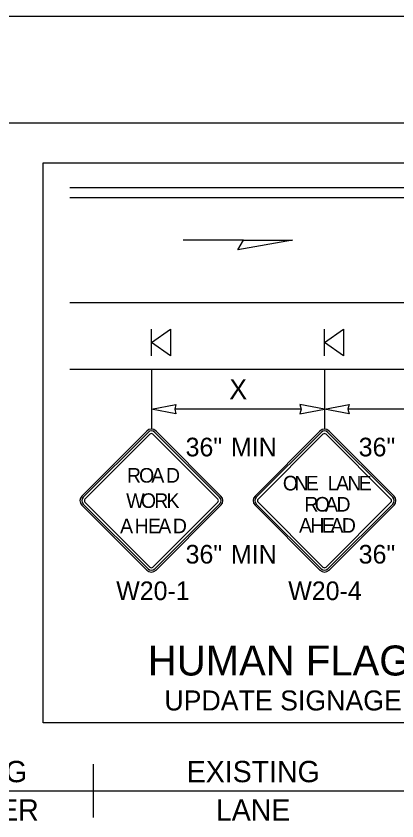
# Model space of a CAD drawing. Extents: x 99999.1 to 100095.7, y 99995 to 100010.7.
# Drawn here: x 100005 to 100006.43, y 100003.112 to 100006.132 of the extents above; entities that cross this region are included whole.
import ezdxf

# ---------------------------------------------------------------- set-up
doc = ezdxf.new("R2010")
doc.units = 0
for name, color, linetype in [('RD_ED_ShoulderPavedEdge', 7, 'Continuous'), ('RD_MK_LineDblYellowCenter', 7, 'Continuous'), ('RD_MK_LineEdgeWhite', 7, 'Continuous'), ('SH_DE_DetailHeading2Text', 7, 'Continuous'), ('TR_SN_ConstructionSigns', 7, 'Continuous'), ('TR_WZ_PortableSignMountBlk-Org', 7, 'Continuous'), ('TR_WZ_WorkZoneDetails', 7, 'Continuous'), ('TR_WZ_WorkZoneTextCurrent', 7, 'Continuous')]:
    doc.layers.add(name, color=color, linetype=linetype)

msp = doc.modelspace()

# ---------------------------------------------------------------- linework, layer by layer
at = {"layer": 'RD_ED_ShoulderPavedEdge'}
for p, q in [((100000.1076, 100005.7323), (100015.6424, 100005.7323)), ((100005.2015, 100004.8073), (100008.9925, 100004.8073))]:
    msp.add_line(p, q, dxfattribs=at)
at = {"layer": 'RD_MK_LineDblYellowCenter'}
for p, q in [((100005.2015, 100005.4886), (100008.0081, 100005.4886)), ((100005.2015, 100005.4511), (100008.0081, 100005.4511))]:
    msp.add_line(p, q, dxfattribs=at)
at = {"layer": 'RD_MK_LineEdgeWhite'}
for p, q in [((100000.1076, 100006.1323), (100015.6424, 100006.1323)), ((100005.2015, 100005.0573), (100008.9925, 100005.0573))]:
    msp.add_line(p, q, dxfattribs=at)
at = {"layer": 'TR_SN_ConstructionSigns'}
for p, q in [((100005.4907, 100004.5751), (100005.2471, 100004.3315)), ((100005.7691, 100004.3315), (100005.5255, 100004.5751)), ((100006.1407, 100004.5751), (100005.8971, 100004.3315)), ((100006.4191, 100004.3315), (100006.1755, 100004.5751)), ((100005.4955, 100004.5703), (100005.2519, 100004.3267)), ((100005.2587, 100004.3199), (100005.5023, 100004.5635)), ((100005.5139, 100004.5635), (100005.7575, 100004.3199)), ((100005.7643, 100004.3267), (100005.5207, 100004.5703)), ((100006.1455, 100004.5703), (100005.9019, 100004.3267)), ((100005.9087, 100004.3199), (100006.1523, 100004.5635)), ((100006.1639, 100004.5635), (100006.4075, 100004.3199)), ((100006.4143, 100004.3267), (100006.1707, 100004.5703)), ((100005.2519, 100004.3015), (100005.4955, 100004.0579)), ((100005.5023, 100004.0647), (100005.2587, 100004.3083)), ((100005.7575, 100004.3083), (100005.5139, 100004.0647)), ((100005.5207, 100004.0579), (100005.7643, 100004.3015)), ((100005.9019, 100004.3015), (100006.1455, 100004.0579)), ((100006.1523, 100004.0647), (100005.9087, 100004.3083)), ((100006.4075, 100004.3083), (100006.1639, 100004.0647)), ((100006.1707, 100004.0579), (100006.4143, 100004.3015)), ((100005.2471, 100004.2967), (100005.4907, 100004.0531)), ((100005.5255, 100004.0531), (100005.7691, 100004.2967)), ((100005.8971, 100004.2967), (100006.1407, 100004.0531)), ((100006.1755, 100004.0531), (100006.4191, 100004.2967))]:
    msp.add_line(p, q, dxfattribs=at)
for centre, radius, start, end in [((100005.5081, 100004.5577), 0.0246, 45, 135), ((100005.5081, 100004.5577), 0.0178, 45, 135), ((100006.1581, 100004.5577), 0.0246, 45, 135), ((100006.1581, 100004.5577), 0.0178, 45, 135), ((100005.5081, 100004.5577), 0.0082, 45, 135), ((100006.1581, 100004.5577), 0.0082, 45, 135), ((100005.2645, 100004.3141), 0.0246, 135, 225), ((100005.7517, 100004.3141), 0.0246, 315, 45), ((100005.9145, 100004.3141), 0.0246, 135, 225), ((100006.4017, 100004.3141), 0.0246, 315, 45), ((100005.2645, 100004.3141), 0.0178, 135, 225), ((100005.2645, 100004.3141), 0.0082, 135, 225), ((100005.7517, 100004.3141), 0.0082, 315, 45), ((100005.7517, 100004.3141), 0.0178, 315, 45), ((100005.9145, 100004.3141), 0.0178, 135, 225), ((100005.9145, 100004.3141), 0.0082, 135, 225), ((100006.4017, 100004.3141), 0.0082, 315, 45), ((100006.4017, 100004.3141), 0.0178, 315, 45), ((100005.5081, 100004.0705), 0.0082, 225, 315), ((100006.1581, 100004.0705), 0.0082, 225, 315), ((100005.5081, 100004.0705), 0.0246, 225, 315), ((100005.5081, 100004.0705), 0.0178, 225, 315), ((100006.1581, 100004.0705), 0.0246, 225, 315), ((100006.1581, 100004.0705), 0.0178, 225, 315)]:
    msp.add_arc(centre, radius, start, end, dxfattribs=at)
at = {"layer": 'TR_WZ_PortableSignMountBlk-Org'}
for p, q in [((100005.5081, 100004.8574), (100005.5081, 100004.9574)), ((100006.1581, 100004.8574), (100006.1581, 100004.9574))]:
    msp.add_line(p, q, dxfattribs=at)
for points in [[(100005.5081, 100004.9073), (100005.5799, 100004.9574), (100005.5799, 100004.8574)], [(100006.1581, 100004.9073), (100006.2299, 100004.9574), (100006.2299, 100004.8574)]]:
    msp.add_lwpolyline(points, close=True, dxfattribs=at)
at = {"layer": 'TR_WZ_WorkZoneDetails'}
for p, q in [((100005.854, 100005.291), (100005.6279, 100005.291)), ((100005.5081, 100004.8073), (100005.5081, 100004.5823)), ((100006.1581, 100004.8073), (100006.1581, 100004.5823)), ((100006.0702, 100004.6573), (100005.596, 100004.6573)), ((100006.7202, 100004.6573), (100006.246, 100004.6573)), ((100005.2907, 100003.1255), (100005.2907, 100003.3255)), ((100004.2907, 100003.2255), (100005.2907, 100003.2255)), ((100005.2907, 100003.2255), (100006.4907, 100003.2255))]:
    msp.add_line(p, q, dxfattribs=at)
for points in [[(100006.0382, 100005.291), (100005.8331, 100005.2549), (100005.854, 100005.291)], [(100005.5081, 100004.6573), (100005.6002, 100004.6754), (100005.596, 100004.6573), (100005.6002, 100004.6393)], [(100006.1581, 100004.6573), (100006.0659, 100004.6754), (100006.0702, 100004.6573), (100006.0659, 100004.6393)], [(100006.1581, 100004.6573), (100006.2502, 100004.6754), (100006.246, 100004.6573), (100006.2502, 100004.6393)]]:
    msp.add_lwpolyline(points, close=True, dxfattribs=at)
at = {"layer": 'TR_WZ_WorkZoneTextCurrent'}
msp.add_lwpolyline([(100005.1015, 100005.5823), (100009.1102, 100005.5823), (100009.1102, 100003.4799), (100005.1015, 100003.4799)], close=True, dxfattribs=at)

# ---------------------------------------------------------------- texts
at = {"layer": 'SH_DE_DetailHeading2Text'}
msp.add_text('HUMAN FLAGGER SUBSTITUTION', height=0.1125, rotation=360, dxfattribs=at).set_placement((100005.4946, 100003.658))
at = {"layer": 'TR_SN_ConstructionSigns'}
for s, p in [('36"', (100005.6365, 100004.4802)), ('MIN', (100005.8071, 100004.4802)), ('36"', (100006.2865, 100004.4802)), ('36"', (100005.6365, 100004.078)), ('MIN', (100005.8071, 100004.078)), ('36"', (100006.2865, 100004.078)), ('W20-1', (100005.376, 100003.9409)), ('W20-4', (100006.022, 100003.9409))]:
    msp.add_text(s, height=0.07, rotation=360, dxfattribs=at).set_placement(p)
for s, p in [('R', (100005.4161, 100004.3817)), ('O', (100005.4618, 100004.3817)), ('A', (100005.5079, 100004.3817)), ('D', (100005.5628, 100004.3817)), ('O', (100006.0017, 100004.3524)), ('N', (100006.0449, 100004.3524)), ('E', (100006.0875, 100004.3524)), ('L', (100006.1701, 100004.3524)), ('A', (100006.2013, 100004.3524)), ('N', (100006.2439, 100004.3524)), ('E', (100006.2866, 100004.3524)), ('W', (100005.4133, 100004.2868)), ('O', (100005.4686, 100004.2868)), ('R', (100005.5187, 100004.2868)), ('K', (100005.5646, 100004.2868)), ('R', (100006.0826, 100004.2731)), ('O', (100006.1214, 100004.2731)), ('A', (100006.1603, 100004.2731)), ('D', (100006.2029, 100004.2731)), ('A', (100005.3905, 100004.1918)), ('H', (100005.4452, 100004.1918)), ('E', (100005.4955, 100004.1918)), ('A', (100005.5338, 100004.1918)), ('D', (100005.5885, 100004.1918)), ('A', (100006.0624, 100004.1938)), ('H', (100006.105, 100004.1938)), ('E', (100006.1477, 100004.1938)), ('A', (100006.1805, 100004.1938)), ('D', (100006.2232, 100004.1938))]:
    msp.add_text(s, height=0.0547, dxfattribs=at).set_placement(p)
at = {"layer": 'TR_WZ_WorkZoneDetails'}
for s, p in [('EXISTING', (100004.5424, 100003.2575)), ('EXISTING', (100005.6409, 100003.2575)), ('SHOULDER', (100004.4905, 100003.1135)), ('LANE', (100005.7503, 100003.1135))]:
    msp.add_text(s, height=0.08, rotation=360, dxfattribs=at).set_placement(p)
at = {"layer": 'TR_WZ_WorkZoneTextCurrent'}
msp.add_text('X', height=0.075, rotation=360, dxfattribs=at).set_placement((100005.8005, 100004.6948))
msp.add_text('UPDATE SIGNAGE & USE STOP/SLOW PADDLE', height=0.075, dxfattribs=at).set_placement((100005.5568, 100003.5268))

doc.saveas('drawing.dxf')
